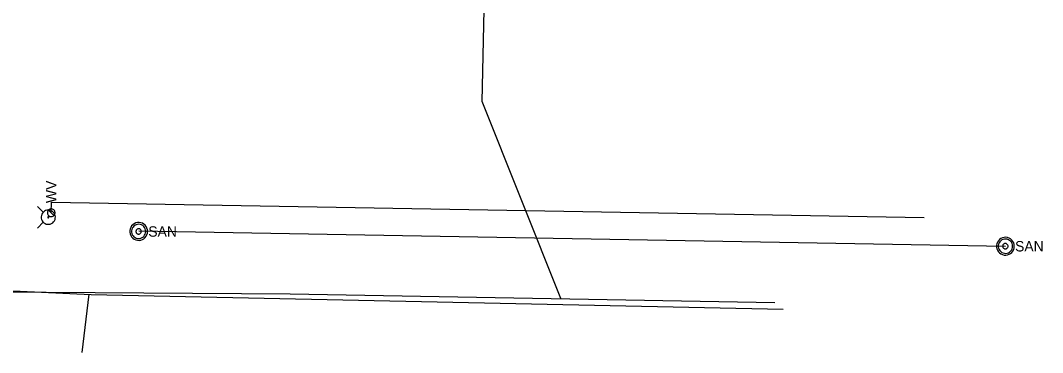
# Model space of a CAD drawing. Extents: x 596028 to 606371, y 330010 to 403088.
# Drawn here: x 604368.9 to 604746.3, y 341947.2 to 342069.8 of the extents above; entities that cross this region are included whole.
import ezdxf

# ---------------------------------------------------------------- set-up
doc = ezdxf.new("R2010")
doc.units = 0
for name, color, linetype in [('E_UTL_G_UG', 7, 'Continuous'), ('E_UTL_Overhead', 7, 'Continuous'), ('E_UTL_SAN_MH', 7, 'Continuous'), ('E_UTL_SAN_UG', 7, 'Continuous'), ('E_UTL_W', 7, 'Continuous'), ('E_UTL_W_UG', 7, 'Continuous'), ('E_UTL_WHydrant', 7, 'Continuous')]:
    doc.layers.add(name, color=color, linetype=linetype)

msp = doc.modelspace()

# ---------------------------------------------------------------- linework, layer by layer
at = {"layer": 'E_UTL_G_UG'}
msp.add_line((604394.95, 341968.63), (604650.44, 341963.22), dxfattribs=at)
for points in [[(604133.81, 341975.21), (604291.12, 341971.55), (604295.4, 341971.48), (604337.18, 341970.45), (604368.79, 341969.89), (604394.95, 341968.63)], [(604394.05, 341968.75), (604391.55, 341947.21)]]:
    msp.add_lwpolyline(points, dxfattribs=at)
at = {"layer": 'E_UTL_Overhead'}
for p, q in [((604343.94, 341969.71), (604468.42, 341968.93)), ((604468.42, 341968.93), (604647.38, 341965.73))]:
    msp.add_line(p, q, dxfattribs=at)
msp.add_lwpolyline([(604568.41, 341967.14), (604539.32, 342039.94), (604547.84, 342429.96), (604565.62, 343244.18), (604495.62, 343245.2)], dxfattribs=at)
at = {"layer": 'E_UTL_SAN_MH'}
for points in [[(604415.8, 341991.92), (604415.74, 341992.54), (604415.56, 341993.14), (604415.27, 341993.7), (604414.89, 341994.19), (604414.41, 341994.6), (604413.87, 341994.92), (604413.28, 341995.12), (604412.66, 341995.21), (604412.03, 341995.18), (604411.42, 341995.04), (604410.85, 341994.77), (604410.34, 341994.41), (604409.9, 341993.96), (604409.57, 341993.43), (604409.33, 341992.85), (604409.21, 341992.23), (604409.21, 341991.6), (604409.33, 341990.99), (604409.57, 341990.4), (604409.9, 341989.88), (604410.34, 341989.42), (604410.85, 341989.06), (604411.42, 341988.8), (604412.03, 341988.65), (604412.66, 341988.62), (604413.28, 341988.71), (604413.87, 341988.92), (604414.41, 341989.23), (604414.89, 341989.64), (604415.27, 341990.13), (604415.56, 341990.69), (604415.74, 341991.29), (604415.8, 341991.92)], [(604415.14, 341991.92), (604415.09, 341992.42), (604414.95, 341992.9), (604414.72, 341993.34), (604414.41, 341993.74), (604414.03, 341994.07), (604413.59, 341994.32), (604413.12, 341994.48), (604412.62, 341994.55), (604412.12, 341994.53), (604411.63, 341994.41), (604411.18, 341994.2), (604410.77, 341993.91), (604410.42, 341993.55), (604410.15, 341993.13), (604409.97, 341992.66), (604409.87, 341992.17), (604409.87, 341991.67), (604409.97, 341991.17), (604410.15, 341990.71), (604410.42, 341990.28), (604410.77, 341989.92), (604411.18, 341989.63), (604411.63, 341989.42), (604412.12, 341989.3), (604412.62, 341989.28), (604413.12, 341989.35), (604413.59, 341989.52), (604414.03, 341989.77), (604414.41, 341990.1), (604414.72, 341990.49), (604414.95, 341990.94), (604415.09, 341991.42), (604415.14, 341991.92)], [(604413.49, 341991.92), (604413.47, 341992.1), (604413.42, 341992.28), (604413.33, 341992.45), (604413.21, 341992.6), (604413.07, 341992.72), (604412.91, 341992.82), (604412.73, 341992.88), (604412.55, 341992.91), (604412.36, 341992.9), (604412.17, 341992.85), (604412, 341992.77), (604411.85, 341992.67), (604411.72, 341992.53), (604411.62, 341992.37), (604411.55, 341992.2), (604411.51, 341992.01), (604411.51, 341991.82), (604411.55, 341991.64), (604411.62, 341991.46), (604411.72, 341991.3), (604411.85, 341991.17), (604412, 341991.06), (604412.17, 341990.98), (604412.36, 341990.94), (604412.55, 341990.93), (604412.73, 341990.95), (604412.91, 341991.02), (604413.07, 341991.11), (604413.21, 341991.23), (604413.33, 341991.38), (604413.42, 341991.55), (604413.47, 341991.73), (604413.49, 341991.92)], [(604735.85, 341986.47), (604735.79, 341987.1), (604735.62, 341987.7), (604735.33, 341988.26), (604734.94, 341988.75), (604734.47, 341989.16), (604733.92, 341989.47), (604733.33, 341989.68), (604732.71, 341989.77), (604732.08, 341989.74), (604731.47, 341989.59), (604730.9, 341989.33), (604730.39, 341988.97), (604729.96, 341988.51), (604729.62, 341987.98), (604729.39, 341987.4), (604729.27, 341986.79), (604729.27, 341986.16), (604729.39, 341985.54), (604729.62, 341984.96), (604729.96, 341984.43), (604730.39, 341983.98), (604730.9, 341983.61), (604731.47, 341983.35), (604732.08, 341983.21), (604732.71, 341983.18), (604733.33, 341983.26), (604733.92, 341983.47), (604734.47, 341983.78), (604734.94, 341984.19), (604735.33, 341984.69), (604735.62, 341985.24), (604735.79, 341985.85), (604735.85, 341986.47)], [(604735.19, 341986.47), (604735.14, 341986.97), (604735, 341987.45), (604734.77, 341987.9), (604734.46, 341988.29), (604734.08, 341988.62), (604733.65, 341988.87), (604733.17, 341989.04), (604732.68, 341989.11), (604732.18, 341989.08), (604731.69, 341988.97), (604731.23, 341988.76), (604730.82, 341988.47), (604730.48, 341988.1), (604730.21, 341987.68), (604730.02, 341987.22), (604729.92, 341986.72), (604729.92, 341986.22), (604730.02, 341985.73), (604730.21, 341985.26), (604730.48, 341984.84), (604730.82, 341984.48), (604731.23, 341984.19), (604731.69, 341983.98), (604732.18, 341983.86), (604732.68, 341983.83), (604733.17, 341983.91), (604733.65, 341984.07), (604734.08, 341984.32), (604734.46, 341984.65), (604734.77, 341985.04), (604735, 341985.49), (604735.14, 341985.97), (604735.19, 341986.47)], [(604733.54, 341986.47), (604733.52, 341986.66), (604733.47, 341986.84), (604733.38, 341987.01), (604733.27, 341987.15), (604733.13, 341987.28), (604732.96, 341987.37), (604732.79, 341987.43), (604732.6, 341987.46), (604732.41, 341987.45), (604732.23, 341987.41), (604732.06, 341987.33), (604731.9, 341987.22), (604731.77, 341987.08), (604731.67, 341986.93), (604731.6, 341986.75), (604731.57, 341986.57), (604731.57, 341986.38), (604731.6, 341986.19), (604731.67, 341986.02), (604731.77, 341985.86), (604731.9, 341985.72), (604732.06, 341985.61), (604732.23, 341985.54), (604732.41, 341985.49), (604732.6, 341985.48), (604732.79, 341985.51), (604732.96, 341985.57), (604733.13, 341985.67), (604733.27, 341985.79), (604733.38, 341985.94), (604733.47, 341986.1), (604733.52, 341986.28), (604733.54, 341986.47)]]:
    msp.add_lwpolyline(points, dxfattribs=at)
at = {"layer": 'E_UTL_SAN_UG'}
msp.add_line((604412.52, 341992.2), (604732.55, 341986.47), dxfattribs=at)
at = {"layer": 'E_UTL_W'}
for points in [[(604380.22, 342000.25), (604379.95, 342000.22), (604379.69, 342000.15), (604379.45, 342000.02), (604379.24, 341999.86), (604379.06, 341999.65), (604378.93, 341999.42), (604378.84, 341999.16), (604378.8, 341998.89), (604378.81, 341998.62), (604378.88, 341998.36), (604378.99, 341998.11), (604379.14, 341997.89), (604379.34, 341997.7), (604379.57, 341997.56), (604379.82, 341997.46), (604380.09, 341997.41), (604380.36, 341997.41), (604380.62, 341997.46), (604380.88, 341997.56), (604381.1, 341997.7), (604381.3, 341997.89), (604381.46, 341998.11), (604381.57, 341998.36), (604381.63, 341998.62), (604381.65, 341998.89), (604381.61, 341999.16), (604381.52, 341999.42), (604381.38, 341999.65), (604381.21, 341999.86), (604380.99, 342000.02), (604380.75, 342000.15), (604380.49, 342000.22), (604380.22, 342000.25)], [(604381.23, 341997.82), (604379.21, 341999.83)]]:
    msp.add_lwpolyline(points, dxfattribs=at)
at = {"layer": 'E_UTL_W_UG'}
msp.add_lwpolyline([(604380.22, 341998.82), (604380.29, 342002.78), (604702.58, 341997.01)], dxfattribs=at)
at = {"layer": 'E_UTL_WHydrant'}
for points in [[(604377.3, 341999), (604375.16, 342001.14)], [(604379.14, 341999.78), (604378.64, 341999.74), (604378.16, 341999.59), (604377.72, 341999.37), (604377.33, 341999.06), (604377, 341998.68), (604376.75, 341998.25), (604376.59, 341997.78), (604376.52, 341997.28), (604376.54, 341996.79), (604376.66, 341996.3), (604376.87, 341995.85), (604377.15, 341995.44), (604377.52, 341995.1), (604377.94, 341994.83), (604378.4, 341994.64), (604378.89, 341994.55), (604379.39, 341994.55), (604379.88, 341994.64), (604380.34, 341994.83), (604380.76, 341995.1), (604381.12, 341995.44), (604381.41, 341995.85), (604381.62, 341996.3), (604381.73, 341996.79), (604381.76, 341997.28), (604381.69, 341997.78), (604381.52, 341998.25), (604381.27, 341998.68), (604380.95, 341999.06), (604380.55, 341999.37), (604380.11, 341999.59), (604379.63, 341999.74), (604379.14, 341999.78)], [(604377.3, 341995.33), (604375.16, 341993.18)], [(604379.14, 341997.36), (604379.1, 341997.36), (604379.06, 341997.35), (604379.03, 341997.33), (604379, 341997.31), (604378.97, 341997.28), (604378.95, 341997.24), (604378.94, 341997.21), (604378.94, 341997.17), (604378.94, 341997.13), (604378.95, 341997.09), (604378.96, 341997.06), (604378.99, 341997.03), (604379.01, 341997), (604379.05, 341996.98), (604379.08, 341996.97), (604379.12, 341996.96), (604379.16, 341996.96), (604379.19, 341996.97), (604379.23, 341996.98), (604379.26, 341997), (604379.29, 341997.03), (604379.31, 341997.06), (604379.33, 341997.09), (604379.34, 341997.13), (604379.34, 341997.17), (604379.33, 341997.21), (604379.32, 341997.24), (604379.3, 341997.28), (604379.28, 341997.31), (604379.25, 341997.33), (604379.21, 341997.35), (604379.17, 341997.36), (604379.14, 341997.36)]]:
    msp.add_lwpolyline(points, dxfattribs=at)

# ---------------------------------------------------------------- texts
at = {"layer": 'E_UTL_SAN_MH'}
for p in [(604416.06, 341989.97), (604736.12, 341984.53)]:
    msp.add_text('SAN', height=3.849, dxfattribs=at).set_placement(p)
at = {"layer": 'E_UTL_W'}
msp.add_text('WV', height=3.85, rotation=90, dxfattribs=at).set_placement((604382.15, 342002.39))

doc.saveas('drawing.dxf')
